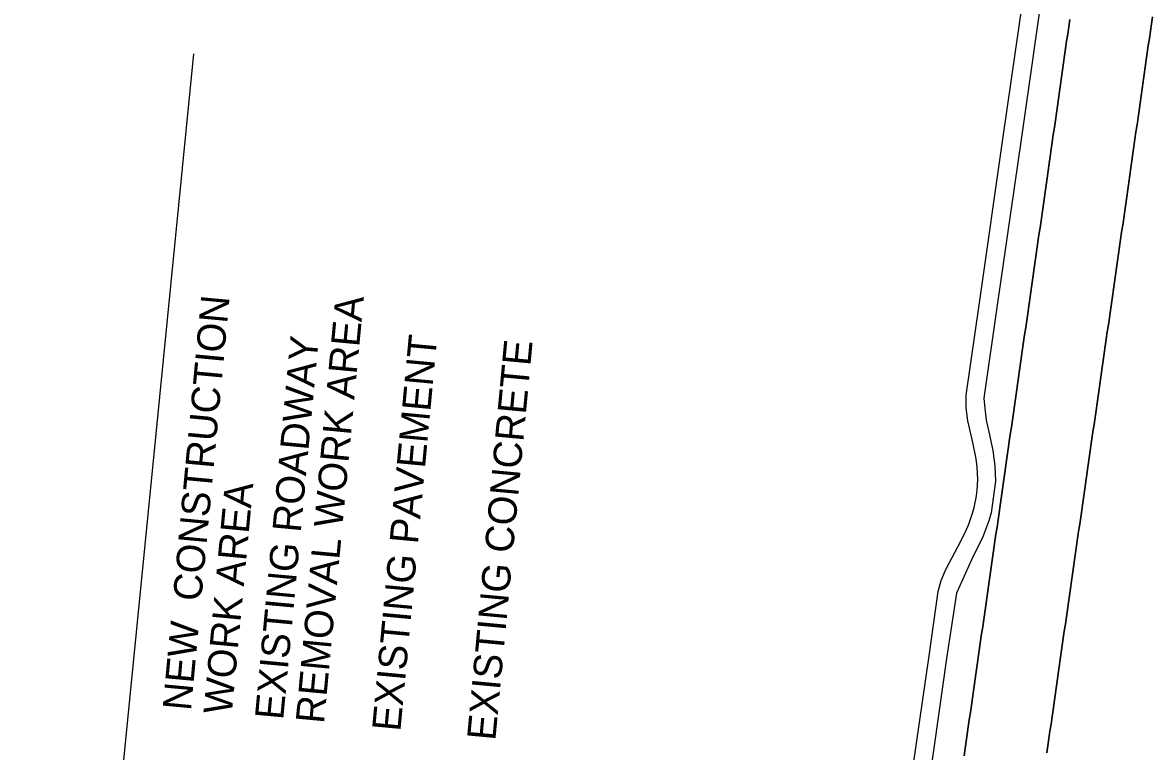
# Model space of a CAD drawing. Extents: x 1795987 to 1799689, y 243690 to 251545.
# Drawn here: x 1797261.4 to 1797571.1, y 247453.1 to 247652.9 of the extents above; entities that cross this region are included whole.
import ezdxf

# ---------------------------------------------------------------- set-up
doc = ezdxf.new("R2010")
doc.units = 0
for name, color, linetype in [('EP', 7, 'Continuous'), ('LEGEND', 7, 'Continuous'), ('Level 62', 7, 'Continuous')]:
    doc.layers.add(name, color=color, linetype=linetype)

msp = doc.modelspace()

# ---------------------------------------------------------------- linework, layer by layer
at = {"layer": 'EP'}
for points in [[(1797502.98, 247431.42), (1797509.89, 247479.28), (1797512.41, 247496.92), (1797513.21, 247499.92), (1797514.39, 247502.79), (1797515.55, 247504.9), (1797517.77, 247509.13), (1797519.86, 247513.31), (1797520.78, 247515.42), (1797521.93, 247518.67), (1797522.28, 247519.96), (1797522.83, 247522.6), (1797523.1, 247524.61), (1797523.26, 247527.63), (1797523.1, 247531.02), (1797522.82, 247533.27), (1797521.91, 247537.81), (1797521.35, 247540.15), (1797520.54, 247543.7), (1797520.12, 247547.31), (1797520.09, 247550.71), (1797523.74, 247576.05), (1797530.2, 247621.54), (1797536.99, 247668.47)], [(1797541.84, 247667.67), (1797535.11, 247620.83), (1797528.62, 247575.39), (1797524.96, 247549.93), (1797525.06, 247548.02), (1797525.55, 247543.91), (1797526.45, 247539.86), (1797526.65, 247538.96), (1797527.41, 247535.59), (1797527.98, 247531.38), (1797528.16, 247527.13), (1797526.97, 247518.48), (1797526.28, 247516.25), (1797524.64, 247511.95), (1797522.63, 247507.8), (1797522.17, 247506.93), (1797521.53, 247505.59), (1797517.43, 247496.48), (1797514.72, 247478.52), (1797507.92, 247430.67)]]:
    msp.add_lwpolyline(points, dxfattribs=at)
at = {"layer": 'LEGEND'}
msp.add_line((1797261.35, 247170.53), (1797308.29, 247644.28), dxfattribs=at)
at = {"layer": 'Level 62'}
for points in [[(1797519.54, 247451.89), (1797519.82, 247453.87), (1797520.1, 247455.84), (1797520.38, 247457.81), (1797520.66, 247459.79), (1797520.94, 247461.76), (1797521.23, 247463.73), (1797521.51, 247465.7), (1797521.79, 247467.68), (1797522.07, 247469.65), (1797522.35, 247471.62), (1797522.63, 247473.59), (1797522.91, 247475.55), (1797523.2, 247477.5), (1797523.48, 247479.45), (1797523.76, 247481.4), (1797524.04, 247483.36), (1797524.32, 247485.31), (1797524.6, 247487.26), (1797524.88, 247489.21), (1797525.16, 247491.17), (1797525.44, 247493.12), (1797525.72, 247495.07), (1797526, 247497.02), (1797526.28, 247498.98), (1797526.56, 247500.93), (1797526.85, 247502.88), (1797527.13, 247504.83), (1797527.41, 247506.79), (1797527.69, 247508.74), (1797527.97, 247510.69), (1797528.25, 247512.64), (1797528.53, 247514.6), (1797528.81, 247516.55), (1797529.09, 247518.5), (1797529.37, 247520.45), (1797529.65, 247522.41), (1797529.93, 247524.36), (1797530.21, 247526.31), (1797530.49, 247528.26), (1797530.78, 247530.22), (1797531.06, 247532.17), (1797531.34, 247534.12), (1797531.62, 247536.07), (1797531.9, 247538.03), (1797532.18, 247539.98), (1797532.46, 247541.93), (1797532.74, 247543.88), (1797533.02, 247545.84), (1797533.3, 247547.79), (1797533.58, 247549.74), (1797533.86, 247551.7), (1797534.14, 247553.65), (1797534.42, 247555.6), (1797534.71, 247557.55), (1797534.99, 247559.51), (1797535.27, 247561.46), (1797535.55, 247563.41), (1797535.83, 247565.36), (1797536.11, 247567.32), (1797536.39, 247569.27), (1797536.67, 247571.22), (1797536.95, 247573.17), (1797537.23, 247575.13), (1797537.51, 247577.08), (1797537.79, 247579.03), (1797538.07, 247580.98), (1797538.35, 247582.94), (1797538.64, 247584.89), (1797538.92, 247586.84), (1797539.2, 247588.79), (1797539.48, 247590.75), (1797539.76, 247592.7), (1797540.04, 247594.65), (1797540.32, 247596.6), (1797540.6, 247598.56), (1797540.88, 247600.51), (1797541.16, 247602.46), (1797541.44, 247604.41), (1797541.72, 247606.37), (1797542, 247608.32), (1797542.29, 247610.27), (1797542.57, 247612.24), (1797542.85, 247614.22), (1797543.13, 247616.19), (1797543.41, 247618.17), (1797543.69, 247620.14), (1797543.97, 247622.11), (1797544.25, 247624.09), (1797544.53, 247626.06), (1797544.81, 247628.04), (1797545.1, 247630.01), (1797545.38, 247631.98), (1797545.66, 247633.96), (1797545.94, 247635.93), (1797546.22, 247637.9), (1797546.5, 247639.88), (1797546.78, 247641.85), (1797547.06, 247643.83), (1797547.34, 247645.8), (1797547.63, 247647.77), (1797547.91, 247649.75), (1797548.19, 247651.72), (1797548.47, 247653.7)], [(1797548.47, 247653.7), (1797548.19, 247651.72), (1797547.91, 247649.75), (1797547.63, 247647.77), (1797547.34, 247645.8), (1797547.06, 247643.83), (1797546.78, 247641.85), (1797546.5, 247639.88), (1797546.22, 247637.9), (1797545.94, 247635.93), (1797545.66, 247633.96), (1797545.38, 247631.98), (1797545.1, 247630.01), (1797544.81, 247628.04), (1797544.53, 247626.06), (1797544.25, 247624.09), (1797543.97, 247622.11), (1797543.69, 247620.14), (1797543.41, 247618.17), (1797543.13, 247616.19), (1797542.85, 247614.22), (1797542.57, 247612.24), (1797542.29, 247610.27), (1797542, 247608.32), (1797541.72, 247606.37), (1797541.44, 247604.41), (1797541.16, 247602.46), (1797540.88, 247600.51), (1797540.6, 247598.56), (1797540.32, 247596.6), (1797540.04, 247594.65), (1797539.76, 247592.7), (1797539.48, 247590.75), (1797539.2, 247588.79), (1797538.92, 247586.84), (1797538.64, 247584.89), (1797538.35, 247582.94), (1797538.07, 247580.98), (1797537.79, 247579.03), (1797537.51, 247577.08), (1797537.23, 247575.13), (1797536.95, 247573.17), (1797536.67, 247571.22), (1797536.39, 247569.27), (1797536.11, 247567.32), (1797535.83, 247565.36), (1797535.55, 247563.41), (1797535.27, 247561.46), (1797534.99, 247559.51), (1797534.71, 247557.55), (1797534.42, 247555.6), (1797534.14, 247553.65), (1797533.86, 247551.7), (1797533.58, 247549.74), (1797533.3, 247547.79), (1797533.02, 247545.84), (1797532.74, 247543.88), (1797532.46, 247541.93), (1797532.18, 247539.98), (1797531.9, 247538.03), (1797531.62, 247536.07), (1797531.34, 247534.12), (1797531.06, 247532.17), (1797530.78, 247530.22), (1797530.49, 247528.26), (1797530.21, 247526.31), (1797529.93, 247524.36), (1797529.65, 247522.41), (1797529.37, 247520.45), (1797529.09, 247518.5), (1797528.81, 247516.55), (1797528.53, 247514.6), (1797528.25, 247512.64), (1797527.97, 247510.69), (1797527.69, 247508.74), (1797527.41, 247506.79), (1797527.13, 247504.83), (1797526.85, 247502.88), (1797526.56, 247500.93), (1797526.28, 247498.98), (1797526, 247497.02), (1797525.72, 247495.07), (1797525.44, 247493.12), (1797525.16, 247491.17), (1797524.88, 247489.21), (1797524.6, 247487.26), (1797524.32, 247485.31), (1797524.04, 247483.36), (1797523.76, 247481.4), (1797523.48, 247479.45), (1797523.2, 247477.5), (1797522.91, 247475.55), (1797522.63, 247473.59), (1797522.35, 247471.62), (1797522.07, 247469.65), (1797521.79, 247467.68), (1797521.51, 247465.7), (1797521.23, 247463.73), (1797520.94, 247461.76), (1797520.66, 247459.79), (1797520.38, 247457.81), (1797520.1, 247455.84), (1797519.82, 247453.87), (1797519.54, 247451.89)], [(1797571.14, 247654.48), (1797570.86, 247652.5), (1797570.58, 247650.53), (1797570.3, 247648.55), (1797570.02, 247646.58), (1797569.74, 247644.61), (1797569.45, 247642.63), (1797569.17, 247640.66), (1797568.89, 247638.69), (1797568.61, 247636.71), (1797568.33, 247634.74), (1797568.05, 247632.77), (1797567.77, 247630.79), (1797567.49, 247628.82), (1797567.21, 247626.84), (1797566.92, 247624.87), (1797566.64, 247622.9), (1797566.36, 247620.92), (1797566.08, 247618.95), (1797565.8, 247616.98), (1797565.52, 247615), (1797565.24, 247613.03), (1797564.96, 247611.05), (1797564.68, 247609.08), (1797564.39, 247607.11), (1797564.11, 247605.15), (1797563.83, 247603.2), (1797563.55, 247601.25), (1797563.27, 247599.3), (1797562.99, 247597.34), (1797562.71, 247595.39), (1797562.43, 247593.44), (1797562.15, 247591.49), (1797561.87, 247589.53), (1797561.59, 247587.58), (1797561.31, 247585.63), (1797561.03, 247583.68), (1797560.75, 247581.72), (1797560.46, 247579.77), (1797560.18, 247577.82), (1797559.9, 247575.87), (1797559.62, 247573.91), (1797559.34, 247571.96), (1797559.06, 247570.01), (1797558.78, 247568.06), (1797558.5, 247566.1), (1797558.22, 247564.15), (1797557.94, 247562.2), (1797557.66, 247560.25), (1797557.38, 247558.29), (1797557.1, 247556.34), (1797556.81, 247554.39), (1797556.53, 247552.43), (1797556.25, 247550.48), (1797555.97, 247548.53), (1797555.69, 247546.58), (1797555.41, 247544.62), (1797555.13, 247542.67), (1797554.85, 247540.72), (1797554.57, 247538.77), (1797554.29, 247536.81), (1797554.01, 247534.86), (1797553.73, 247532.91), (1797553.45, 247530.96), (1797553.17, 247529), (1797552.88, 247527.05), (1797552.6, 247525.1), (1797552.32, 247523.15), (1797552.04, 247521.19), (1797551.76, 247519.24), (1797551.48, 247517.29), (1797551.2, 247515.34), (1797550.92, 247513.38), (1797550.64, 247511.43), (1797550.36, 247509.48), (1797550.08, 247507.53), (1797549.8, 247505.57), (1797549.52, 247503.62), (1797549.23, 247501.67), (1797548.95, 247499.72), (1797548.67, 247497.76), (1797548.39, 247495.81), (1797548.11, 247493.86), (1797547.83, 247491.91), (1797547.55, 247489.95), (1797547.27, 247488), (1797546.99, 247486.05), (1797546.71, 247484.09), (1797546.43, 247482.14), (1797546.15, 247480.19), (1797545.87, 247478.24), (1797545.59, 247476.28), (1797545.3, 247474.33), (1797545.02, 247472.38), (1797544.74, 247470.43), (1797544.46, 247468.45), (1797544.18, 247466.48), (1797543.9, 247464.51), (1797543.62, 247462.54), (1797543.34, 247460.56), (1797543.05, 247458.59), (1797542.77, 247456.62), (1797542.49, 247454.65), (1797542.21, 247452.67)], [(1797542.21, 247452.67), (1797542.49, 247454.65), (1797542.77, 247456.62), (1797543.05, 247458.59), (1797543.34, 247460.56), (1797543.62, 247462.54), (1797543.9, 247464.51), (1797544.18, 247466.48), (1797544.46, 247468.45), (1797544.74, 247470.43), (1797545.02, 247472.38), (1797545.3, 247474.33), (1797545.59, 247476.28), (1797545.87, 247478.24), (1797546.15, 247480.19), (1797546.43, 247482.14), (1797546.71, 247484.09), (1797546.99, 247486.05), (1797547.27, 247488), (1797547.55, 247489.95), (1797547.83, 247491.91), (1797548.11, 247493.86), (1797548.39, 247495.81), (1797548.67, 247497.76), (1797548.95, 247499.72), (1797549.23, 247501.67), (1797549.52, 247503.62), (1797549.8, 247505.57), (1797550.08, 247507.53), (1797550.36, 247509.48), (1797550.64, 247511.43), (1797550.92, 247513.38), (1797551.2, 247515.34), (1797551.48, 247517.29), (1797551.76, 247519.24), (1797552.04, 247521.19), (1797552.32, 247523.15), (1797552.6, 247525.1), (1797552.88, 247527.05), (1797553.17, 247529), (1797553.45, 247530.96), (1797553.73, 247532.91), (1797554.01, 247534.86), (1797554.29, 247536.81), (1797554.57, 247538.77), (1797554.85, 247540.72), (1797555.13, 247542.67), (1797555.41, 247544.62), (1797555.69, 247546.58), (1797555.97, 247548.53), (1797556.25, 247550.48), (1797556.53, 247552.43), (1797556.81, 247554.39), (1797557.1, 247556.34), (1797557.38, 247558.29), (1797557.66, 247560.25), (1797557.94, 247562.2), (1797558.22, 247564.15), (1797558.5, 247566.1), (1797558.78, 247568.06), (1797559.06, 247570.01), (1797559.34, 247571.96), (1797559.62, 247573.91), (1797559.9, 247575.87), (1797560.18, 247577.82), (1797560.46, 247579.77), (1797560.75, 247581.72), (1797561.03, 247583.68), (1797561.31, 247585.63), (1797561.59, 247587.58), (1797561.87, 247589.53), (1797562.15, 247591.49), (1797562.43, 247593.44), (1797562.71, 247595.39), (1797562.99, 247597.34), (1797563.27, 247599.3), (1797563.55, 247601.25), (1797563.83, 247603.2), (1797564.11, 247605.15), (1797564.39, 247607.11), (1797564.68, 247609.08), (1797564.96, 247611.05), (1797565.24, 247613.03), (1797565.52, 247615), (1797565.8, 247616.98), (1797566.08, 247618.95), (1797566.36, 247620.92), (1797566.64, 247622.9), (1797566.92, 247624.87), (1797567.21, 247626.84), (1797567.49, 247628.82), (1797567.77, 247630.79), (1797568.05, 247632.77), (1797568.33, 247634.74), (1797568.61, 247636.71), (1797568.89, 247638.69), (1797569.17, 247640.66), (1797569.45, 247642.63), (1797569.74, 247644.61), (1797570.02, 247646.58), (1797570.3, 247648.55), (1797570.58, 247650.53), (1797570.86, 247652.5), (1797571.14, 247654.48)]]:
    msp.add_lwpolyline(points, dxfattribs=at)

# ---------------------------------------------------------------- texts
at = {"layer": 'LEGEND'}
for s, height, p in [('NEW  CONSTRUCTION', 7.7999, (1797307.5, 247464.07)), ('REMOVAL WORK AREA', 7.7999, (1797343.98, 247460.51)), ('EXISTING ROADWAY', 7.7999, (1797332.79, 247461.56)), ('EXISTING PAVEMENT', 7.7999, (1797364.92, 247458.39)), ('EXISTING CONCRETE', 7.7999, (1797390.96, 247455.89)), ('WORK AREA', 7.8, (1797318.69, 247463.02))]:
    msp.add_text(s, height=height, rotation=84.6544, dxfattribs=at).set_placement(p)

doc.saveas('drawing.dxf')
